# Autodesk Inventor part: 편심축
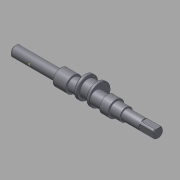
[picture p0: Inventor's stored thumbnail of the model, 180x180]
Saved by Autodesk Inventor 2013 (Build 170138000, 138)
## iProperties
Company: 한국ATC센터
Created: 2015-12
Part Number: 편심축
Document SubType Name: Modeling
Designer: mdu
Density: 7.86 g/cm^3
Mass: 232.042 g
Surface Area: 95.1306 cm^2
Volume: 29.5219 cm^3
Material: 강철, 연강
Author: mdu
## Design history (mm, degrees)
sketch "스케치1"
  geometry: L1 (-84.5, 0)-(84.5, 0); L2 (-84.5, 0)-(-84.5, 6); L3 (-84.5, 6)-(-30.5, 6); L4 (-30.5, 6)-(-30.5, 9.5); L5 (-30.5, 9.5)-(-15.5, 9.5); L6 (-15.5, 9.5)-(-15.5, 7.5); L7 (-15.5, 7.5)-(46.5, 7.5); L8 (84.5, 6)-(84.5, 0); L9 (34.5, 7.5)-(34.5, 9.5); L10 (34.5, 9.5)-(24.5, 9.5); L11 (24.5, 9.5)-(24.5, 7.5); L12 (46.5, 7.5)-(46.5, 6); L13 (46.5, 6)-(84.5, 6); 2 further points
  constraints: 26 end point, 6 parallel, 6 perpendicular, 2 point on line, 1 coincident, 1 horizontal, 1 midpoint
  dimensions: "d1" = 12 diameter of L3 L1; "d2" = 15 diameter of L7 L1; "d4" = 15 distance of L4.end L5.end; "d5" = 19 diameter of L5 L1; "d24" = 10 distance of L9.end L10.end; "d25" = 19 diameter of L10 L1; "d27" = 40 distance between parallel lines of L11 L6; "d28" = 54 distance of L2.end L3.end; "d29" = 50 distance between parallel lines of L8 L9; "d41" = 38 distance between parallel lines of L8 L12; "d42" = 12 diameter of L13 L1
revolve "회전1" stored, may be unused: angle "d6" = 90 deg
node "작업 평면1"
sketch "스케치2"
  geometry: C1 r 7.5 at (0, 0) reference; C2 r 12.5 at (0, 4.5); 1 further point
  constraints: 1 centre point, 1 vertical alignment
  dimensions: "d8" = 4.5 distance of point (0, 0) C2.centre; "d9" = 25 diameter of C2
extrude "돌출1" join sketch "스케치2" distance "d10" = 18; taper "d11" = 0 deg
chamfer "모따기1" distance "d12" = 1; stored, may be unused: second distance "d13" = 2, angle "d14" = 45 deg
chamfer "모따기2" distance "d15" = 0.5; stored, may be unused: second distance "d16" = 2, angle "d17" = 45 deg
node "작업 평면2"
sketch "스케치3"
  geometry: L1 (4, -2)-(18, -2); L2 (18, 2)-(4, 2); L3 (27, 5)-(27, -5) reference; A1 r 2 centre (18, 0) between (18, -2) and (18, 2); A2 r 2 centre (4, 0) between (4, 2) and (4, -2); 2 further points
  constraints: 4 end point, 4 point on circle, 4 tangent, 2 centre point, 1 horizontal, 1 horizontal alignment, 1 midpoint, 1 parallel
  dimensions: "d18" = 7 distance edge to line of A1 L3; "d19" = 4 distance between parallel lines of L2 L1; "d20" = 18 dimension on A1 A2
extrude "돌출2" cut sketch "스케치3" distance "d21" = 2.5; taper "d22" = 0 deg
revolve "회전2" stored, may be unused: angle "d26" = 90 deg
node "작업 평면3"
sketch "스케치10"
  geometry: L1 (-5, -5)-(5, -5); L2 (5, -5)-(5, 5); L3 (5, 5)-(-5, 5); L4 (-5, 5)-(-5, -5); L5 (-5, -5)-(5, 5); L6 (5, -5)-(-5, 5); C1 r 5 at (0, 0) reference; C2 r 6 at (0, 0) reference; A1 r 6 centre (0, 0) between (5, 3.317) and (3.317, 5); A2 r 6 centre (0, 0) between (5, -3.317) and (5, 3.317); A3 r 6 centre (0, 0) between (3.317, -5) and (5, -3.317); A4 r 6 centre (0, 0) between (-3.317, -5) and (3.317, -5); A5 r 6 centre (0, 0) between (-5, -3.317) and (-3.317, -5); A6 r 6 centre (0, 0) between (-5, 3.317) and (-5, -3.317); A7 r 6 centre (0, 0) between (-3.317, 5) and (-5, 3.317); A8 r 6 centre (0, 0) between (3.317, 5) and (-3.317, 5)
  constraints: 16 point on circle, 12 end point, 8 centre point, 8 point on line, 2 midpoint, 2 parallel, 2 tangent, 1 coincident, 1 concentric, 1 horizontal, 1 perpendicular
extrude "돌출4" cut sketch "스케치10" distance "d55" = 17; taper "d56" = 0 deg
sketch "스케치6"
  geometry: L1 (-83.5, -6)-(-30.5, -6) reference; L2 (-84.5, -5)-(-84.5, 5) reference; L3 (-83.5, 6)-(-30.5, 6) reference; L4 (-62.5, 6)-(-62.5, -6); L5 (-62.5, -6)-(-61, -6); L6 (-62.5, -4.5)-(-61, -6); L7 (-62.5, -6)-(-62.5, -4.5); 2 further points
  constraints: 8 end point, 4 point on line, 2 perpendicular, 1 coincident
  dimensions: "d43" = 22 distance between parallel lines of L4 L2; "d44" = 45 deg angle of L6 L7; "d45" = 3 diameter of L5.end L4
revolve "회전3" stored, may be unused: angle "d46" = 90 deg
node "작업점1"
node "작업 평면5"
sketch "스케치11"
  geometry: C1 r 12.5 at (0, 0) reference; C2 r 9.5 at (0, 0); 1 further point
  constraints: 1 centre point
  dimensions: "d57" = 3 radial gap between concentric circles of C1 C2
extrude "돌출5" cut sketch "스케치11" stored distance "d58" = 11; taper "d59" = 0 deg
fillet "모깎기1" dims "d60" = 0.3
chamfer "모따기4" distance "d61" = 0.5; stored, may be unused: second distance "d62" = 2, angle "d63" = 45 deg
node "솔리드1"
node "절단 모서리 투영2"
other parameters: "d7" = 8.5
